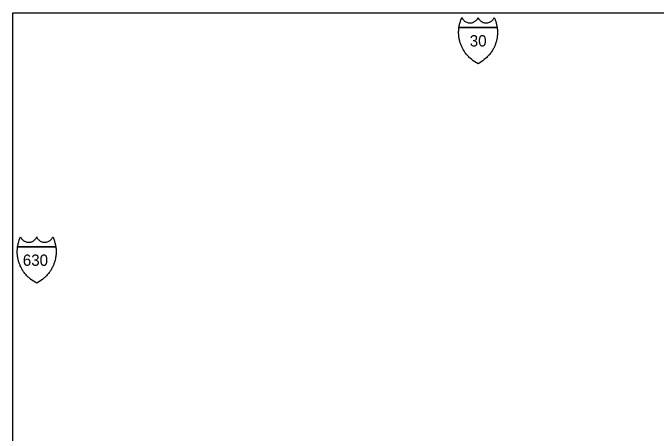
# Model space of a CAD drawing. Extents: x 759117 to 1215197, y 961017 to 2072683.
# Drawn here: x 759117 to 838885, y 1013133 to 1065249 of the extents above; entities that cross this region are included whole.
import ezdxf

# ---------------------------------------------------------------- set-up
doc = ezdxf.new("R2010")
doc.units = 0
for name, color, linetype in [('23', 7, 'Continuous'), ('G-ANNO-TEXT', 7, 'Continuous'), ('NO PLOT CELL', 7, 'Continuous')]:
    doc.layers.add(name, color=color, linetype=linetype)

msp = doc.modelspace()

# ---------------------------------------------------------------- linework, layer by layer
at = {"layer": '23'}
for points in [[(814438, 1063430), (814455, 1063543), (814473, 1063643), (814500, 1063772), (814519, 1063856), (814544, 1063956), (814577, 1064073), (814607, 1064171), (814641, 1064272), (814686, 1064396), (814733, 1064513), (814771, 1064603), (814804, 1064674), (814838, 1064597), (814879, 1064524), (814923, 1064457), (814980, 1064383), (815026, 1064332), (815082, 1064278), (815139, 1064230), (815201, 1064185), (815299, 1064126), (815400, 1064079), (815491, 1064047), (815581, 1064024), (815677, 1064008), (815790, 1064001), (815864, 1064002), (815948, 1064010), (816024, 1064023), (816105, 1064043), (816186, 1064070), (816295, 1064118), (816371, 1064160), (816459, 1064220), (816543, 1064291), (816604, 1064353), (816674, 1064438), (816732, 1064525), (816766, 1064585), (816803, 1064665)], [(816803, 1064665), (816841, 1064585), (816875, 1064525), (816932, 1064438), (817003, 1064353), (817064, 1064291), (817148, 1064220), (817236, 1064160), (817311, 1064118), (817421, 1064070), (817502, 1064043), (817583, 1064023), (817658, 1064010), (817743, 1064002), (817817, 1064001), (817929, 1064008), (818026, 1064024), (818116, 1064047), (818207, 1064079), (818308, 1064126), (818406, 1064185), (818468, 1064230), (818524, 1064278), (818581, 1064332), (818626, 1064383), (818684, 1064457), (818728, 1064524), (818768, 1064597), (818803, 1064674), (818835, 1064603), (818874, 1064513), (818920, 1064396), (818965, 1064272), (818999, 1064171), (819029, 1064073), (819062, 1063956), (819088, 1063856), (819107, 1063772), (819134, 1063643), (819152, 1063543), (819169, 1063430)], [(816803, 1058949), (816596, 1059059), (816414, 1059169), (816213, 1059304), (816026, 1059446), (815821, 1059621), (815745, 1059692), (815658, 1059777), (815577, 1059860), (815489, 1059957), (815403, 1060057), (815330, 1060146), (815252, 1060248), (815181, 1060347), (815119, 1060437), (815065, 1060521), (815021, 1060593), (814961, 1060694), (814915, 1060776), (814865, 1060873), (814815, 1060973), (814773, 1061066), (814734, 1061155), (814693, 1061255), (814658, 1061348), (814623, 1061445), (814590, 1061546), (814559, 1061650), (814532, 1061749), (814509, 1061843), (814489, 1061927), (814476, 1061989), (814454, 1062109), (814432, 1062248), (814418, 1062364), (814407, 1062486), (814401, 1062585), (814396, 1062710), (814395, 1062827), (814397, 1062958), (814401, 1063043), (814406, 1063122), (814409, 1063171), (814421, 1063299), (814438, 1063430)], [(819169, 1063430), (814438, 1063430)], [(814438, 1063430), (819169, 1063430)], [(819169, 1063430), (819185, 1063299), (819197, 1063171), (819201, 1063122), (819206, 1063043), (819209, 1062958), (819212, 1062827), (819211, 1062710), (819206, 1062585), (819200, 1062486), (819189, 1062364), (819174, 1062248), (819153, 1062109), (819130, 1061989), (819117, 1061927), (819098, 1061843), (819075, 1061749), (819048, 1061650), (819017, 1061546), (818983, 1061445), (818949, 1061348), (818914, 1061255), (818873, 1061155), (818834, 1061066), (818791, 1060973), (818742, 1060873), (818691, 1060776), (818645, 1060694), (818586, 1060593), (818542, 1060521), (818487, 1060437), (818426, 1060347), (818355, 1060248), (818276, 1060146), (818204, 1060057), (818118, 1059957), (818029, 1059860), (817949, 1059777), (817862, 1059692), (817786, 1059621), (817581, 1059446), (817394, 1059304), (817193, 1059169), (817011, 1059059), (816803, 1058949)], [(759707, 1036228), (759725, 1036341), (759742, 1036441), (759769, 1036570), (759788, 1036654), (759814, 1036754), (759847, 1036871), (759877, 1036969), (759911, 1037070), (759956, 1037194), (760002, 1037310), (760041, 1037401), (760073, 1037472), (760108, 1037395), (760148, 1037322), (760192, 1037255), (760250, 1037180), (760295, 1037130), (760352, 1037075), (760408, 1037028), (760470, 1036983), (760568, 1036924), (760669, 1036877), (760760, 1036845), (760850, 1036822), (760947, 1036806), (761059, 1036798), (761133, 1036800), (761218, 1036808), (761293, 1036821), (761374, 1036840), (761455, 1036867), (761565, 1036916), (761640, 1036958), (761728, 1037018), (761812, 1037089), (761873, 1037151), (761944, 1037236), (762001, 1037322), (762035, 1037383), (762073, 1037463)], [(762073, 1037463), (762110, 1037383), (762144, 1037322), (762202, 1037236), (762272, 1037151), (762333, 1037089), (762417, 1037018), (762505, 1036958), (762581, 1036916), (762690, 1036867), (762771, 1036840), (762852, 1036821), (762928, 1036808), (763012, 1036800), (763086, 1036798), (763199, 1036806), (763295, 1036822), (763385, 1036845), (763476, 1036877), (763577, 1036924), (763675, 1036983), (763737, 1037028), (763794, 1037075), (763850, 1037130), (763896, 1037180), (763953, 1037255), (763997, 1037322), (764038, 1037395), (764072, 1037472), (764105, 1037401), (764143, 1037310), (764190, 1037194), (764235, 1037070), (764269, 1036969), (764299, 1036871), (764332, 1036754), (764357, 1036654), (764377, 1036570), (764403, 1036441), (764421, 1036341), (764438, 1036228)], [(762073, 1031746), (761865, 1031857), (761683, 1031967), (761482, 1032102), (761295, 1032244), (761090, 1032418), (761014, 1032490), (760927, 1032575), (760847, 1032658), (760758, 1032754), (760672, 1032855), (760600, 1032944), (760521, 1033046), (760450, 1033144), (760389, 1033235), (760334, 1033318), (760290, 1033390), (760231, 1033491), (760185, 1033574), (760134, 1033671), (760085, 1033771), (760042, 1033863), (760003, 1033953), (759962, 1034053), (759927, 1034146), (759893, 1034243), (759859, 1034344), (759828, 1034447), (759801, 1034546), (759778, 1034640), (759759, 1034724), (759746, 1034786), (759723, 1034907), (759702, 1035046), (759687, 1035162), (759676, 1035284), (759670, 1035383), (759665, 1035508), (759664, 1035625), (759666, 1035755), (759670, 1035841), (759675, 1035920), (759679, 1035969), (759691, 1036097), (759707, 1036228)], [(764438, 1036228), (759707, 1036228)], [(759707, 1036228), (764438, 1036228)], [(764438, 1036228), (764455, 1036097), (764467, 1035969), (764470, 1035920), (764475, 1035841), (764479, 1035755), (764481, 1035625), (764480, 1035508), (764475, 1035383), (764469, 1035284), (764458, 1035162), (764444, 1035046), (764422, 1034907), (764400, 1034786), (764387, 1034724), (764368, 1034640), (764344, 1034546), (764317, 1034447), (764286, 1034344), (764253, 1034243), (764218, 1034146), (764183, 1034053), (764142, 1033953), (764103, 1033863), (764061, 1033771), (764011, 1033671), (763961, 1033574), (763915, 1033491), (763855, 1033390), (763811, 1033318), (763757, 1033235), (763695, 1033144), (763624, 1033046), (763546, 1032944), (763473, 1032855), (763387, 1032754), (763299, 1032658), (763218, 1032575), (763131, 1032490), (763055, 1032418), (762850, 1032244), (762663, 1032102), (762462, 1031967), (762280, 1031857), (762073, 1031746)]]:
    msp.add_lwpolyline(points, dxfattribs=at)
at = {"layer": 'NO PLOT CELL'}
msp.add_lwpolyline([(875318, 1065249), (875318, 1050499), (888818, 1050499), (888818, 1060294), (918653, 1060294), (918653, 1045544), (918653, 961017), (759117, 961017), (759117, 1065249)], close=True, dxfattribs=at)

# ---------------------------------------------------------------- texts
at = {"layer": 'G-ANNO-TEXT'}
for s, p in [('30', (815775, 1061081)), ('630', (760353, 1033879))]:
    msp.add_text(s, height=1402.1, dxfattribs=at).set_placement(p)

doc.saveas('drawing.dxf')
